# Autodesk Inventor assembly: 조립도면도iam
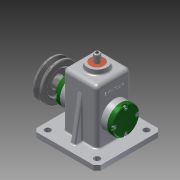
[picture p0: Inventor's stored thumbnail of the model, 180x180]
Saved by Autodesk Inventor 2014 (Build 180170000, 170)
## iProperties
Created: 2016-02
Part Number: 조립도면도iam
Document SubType Name: Assembly
Designer: aapexcom
Author: aapexcom
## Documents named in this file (16)
- C:\Users\aapexcom\Desktop\460212V1009\조립도면도iam.iam
- C:\Users\aapexcom\Desktop\460212V1009\본체.ipt
- C:\Users\aapexcom\Desktop\460212V1009\앞커버.ipt
- C:\Users\aapexcom\Desktop\460212V1009\뒤커버.ipt
- C:\Users\aapexcom\Desktop\460212V1009\편심축.ipt
- C:\Users\aapexcom\Desktop\460212V1009\베어링 12 x 32 x 10.ipt
- C:\Users\aapexcom\Desktop\460212V1009\오일실 12 25 7.ipt
- C:\Users\aapexcom\Desktop\460212V1009\V벨트풀리.ipt
- C:\Users\aapexcom\Desktop\460212V1009\키 4 x 4 x 10.ipt
- C:\Users\aapexcom\Desktop\460212V1009\멈춤나사 M3x8.ipt
- C:\Users\aapexcom\Desktop\460212V1009\볼트 M4 x 12.ipt
- C:\Users\aapexcom\Desktop\460212V1009\링크.ipt
- C:\Users\aapexcom\Desktop\460212V1009\슬라이드.ipt
- C:\Users\aapexcom\Desktop\460212V1009\핀 5 x 18.ipt
- C:\Users\aapexcom\Desktop\460212V1009\고정핀 1.2 x 10.ipt
- C:\Users\aapexcom\Desktop\460212V1009\부시.ipt
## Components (11 placed, 4 different names)
1. V벨트풀리:1 — 각도:1
2. 핀 5 x 18:1
3. 고정핀 1.2 x 10:1
4. ISO 4762 M4 x 12:2
5. ISO 4762 M4 x 12:3
6. ISO 4762 M4 x 12:4
7. ISO 4762 M4 x 12:5
8. ISO 4762 M4 x 12:1
9. ISO 4762 M4 x 12:6
10. ISO 4762 M4 x 12:7
11. ISO 4762 M4 x 12:8
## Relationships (1: Angle 1)
- 각도:1 [Angle]: V벨트풀리:1
